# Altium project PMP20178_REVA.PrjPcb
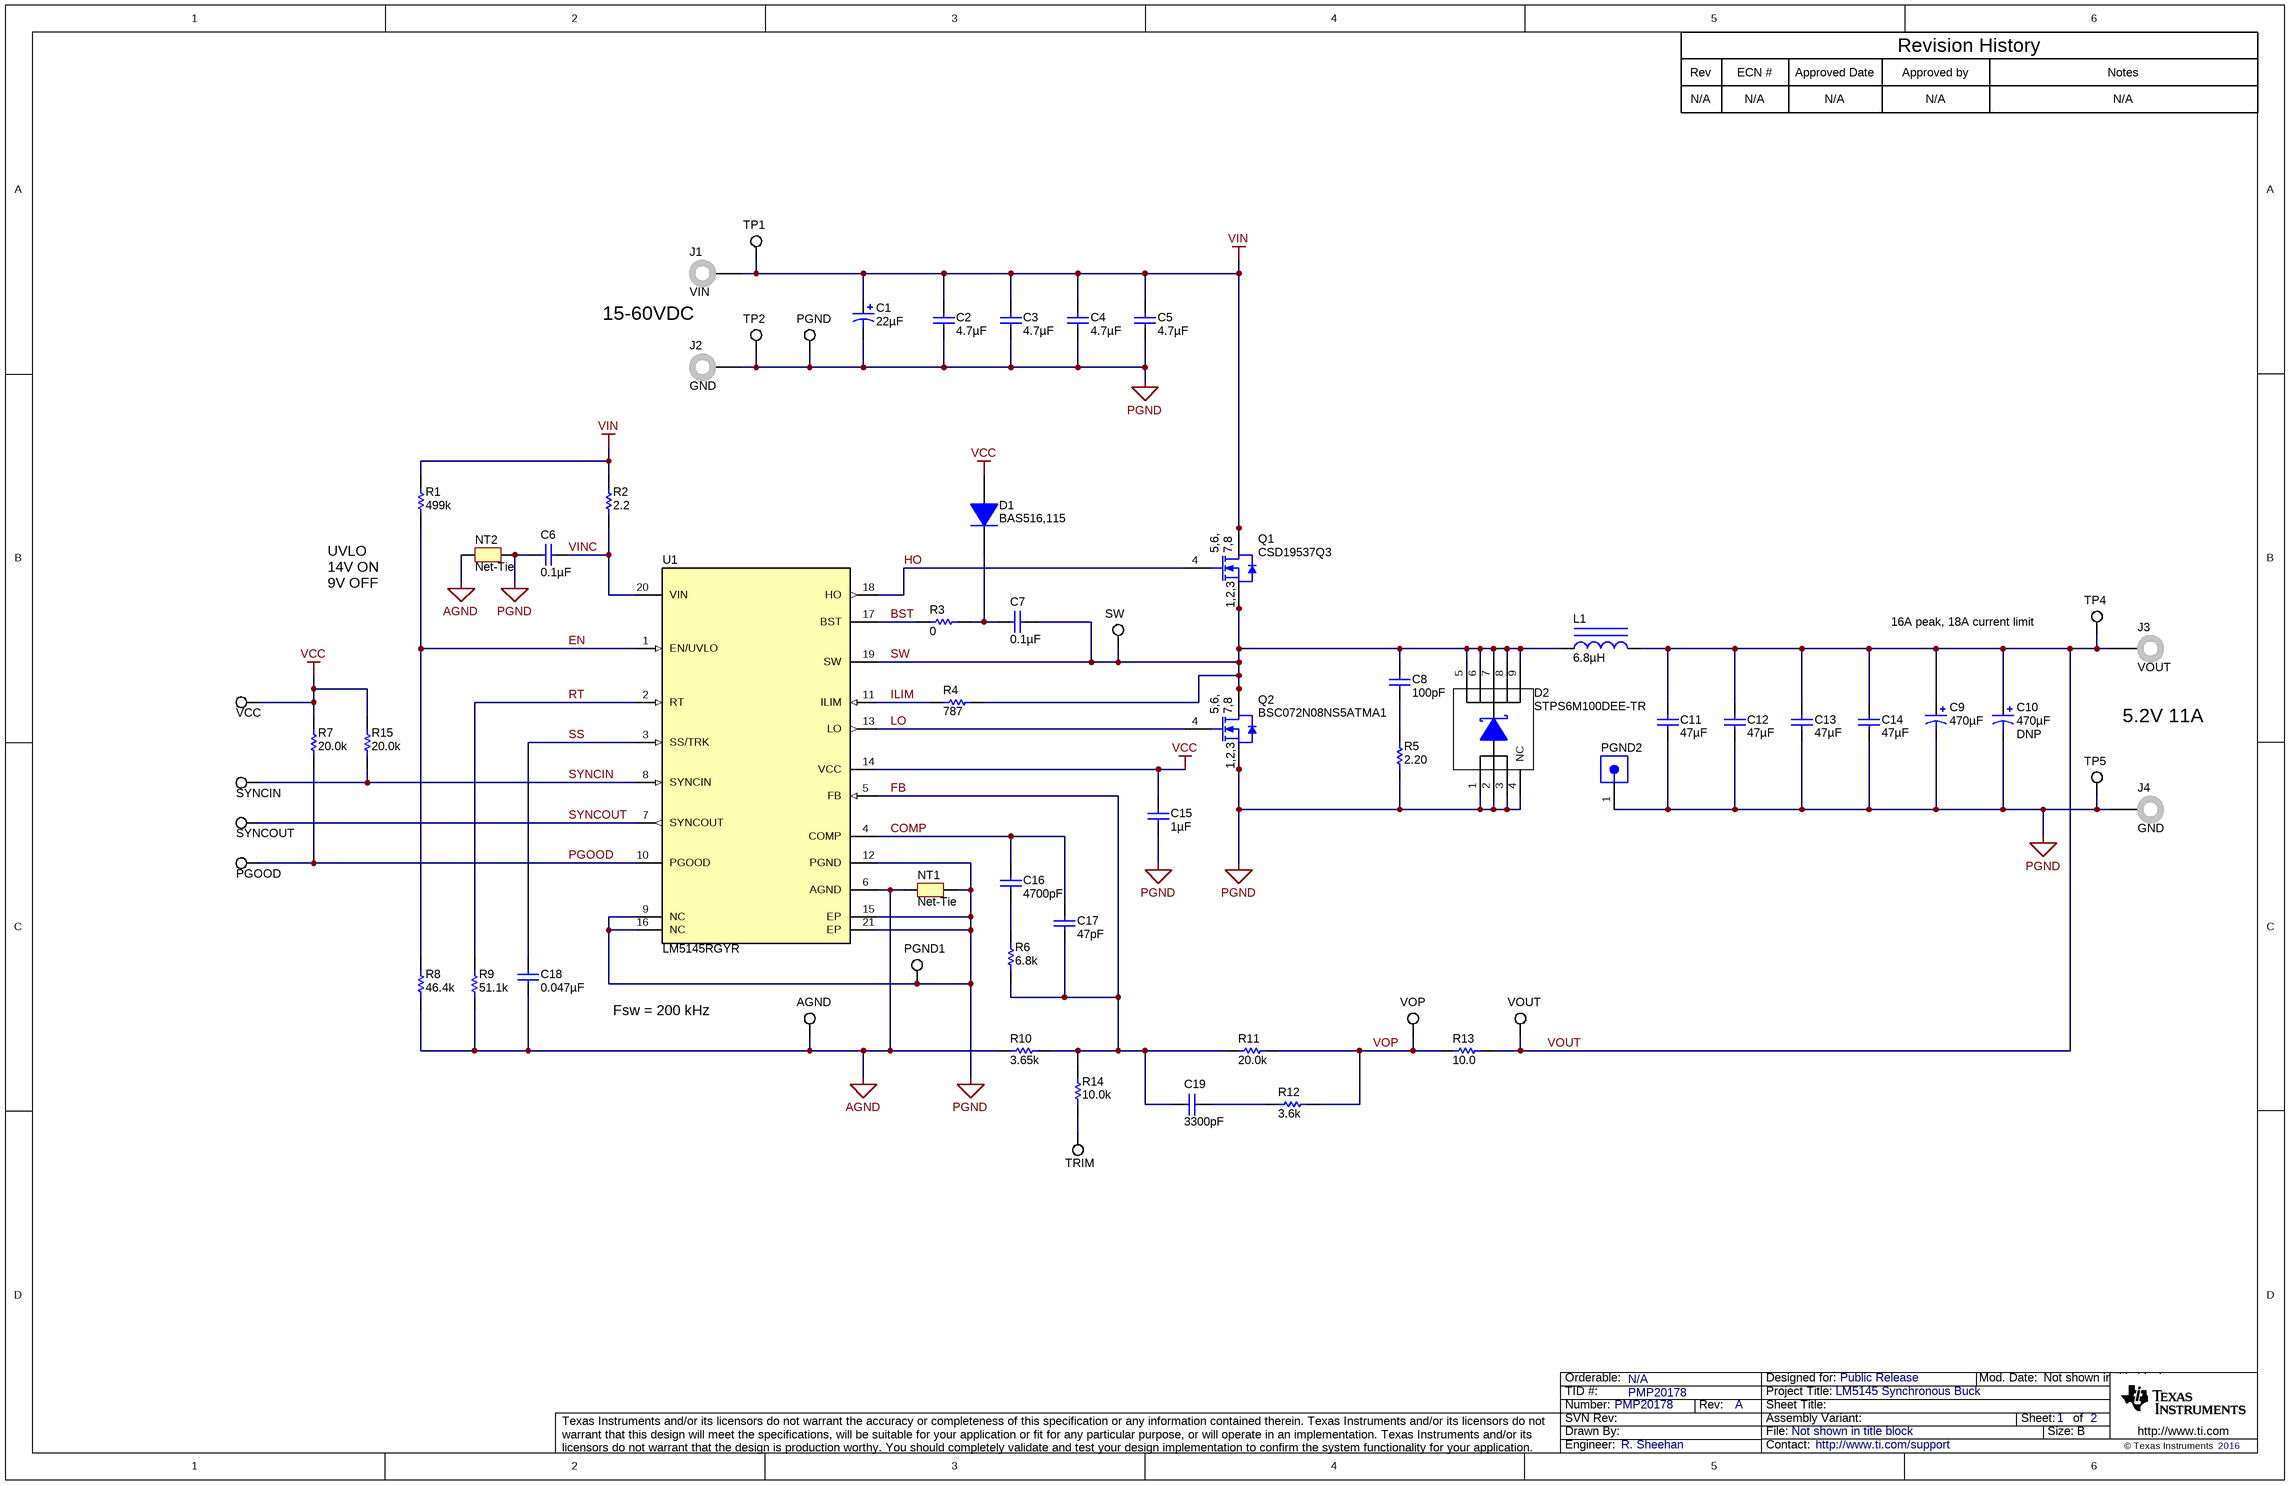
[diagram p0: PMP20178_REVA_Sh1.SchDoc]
CopyrightYear: 2016; EVM_Orderable: N/A; PCB_Layout: R. Sheehan; PCB_Rev: A; PRJ_Customer: Public Release; PRJ_Engineer: R. Sheehan; PRJ_Number: PMP20178; PRJ_Title: LM5145 Synchronous Buck; SCH_Rev: A; TechSupport: http://www.ti.com/support; TID: PMP20178
2 sheets, 79 parts. Net scope: global (net labels, ports and power ports of the same name join across sheets).
Board file: PMP20178_REVA.PcbDoc
Sheets:
  PMP20178_REVA_Sh1.SchDoc
  PMP20178_REVA_Sh2.SchDoc

## Sheet PMP20178_REVA_Sh1.SchDoc
size 431 x 279 mm; Date: Not shown in title block; ApprovedBy: Not shown in title block; CheckedBy: Not shown in title block; Author: Not shown in title block; CompanyName: Not shown in title block; Engineer: Not shown in title block; Organization: Not shown in title block; Address1: Not shown in title block; Address2: Not shown in title block; Address3: Not shown in title block; Address4: Not shown in title block; DocumentNumber: 1; Revision: Use project parameter SCH_Rev; SheetNumber: 1; SheetTotal: 2; PageSetup: Record=PageOptions¦CenterHorizontal=True¦CenterVertical=True¦PrintScale=1.00¦XCorrection=1.00¦YCorrection=1.00¦PrintKind=0¦BorderSize=5000000¦LeftOffset=0¦BottomOffset=0¦Orientation=2¦PaperLength=1000¦PaperWidth=1000¦Scale=100¦PaperSource=15¦PrintQuality=600¦MediaType=1¦DitherType=10¦PaperKind=Letter¦PrintScaleMode=1

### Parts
AGND  5015  [Testpoint_Keystone_Miniature]  (value not drawn)
C1  ValueDisplayed: 22µF  [SM_RADIAL_F]  (hidden comment: EEE-FK2A220P)
C2  ValueDisplayed: 4.7µF  [1210]  (hidden comment: C3225X7S2A475K200AB)
C3  ValueDisplayed: 4.7µF  [1210]  (hidden comment: C3225X7S2A475K200AB)
C4  ValueDisplayed: 4.7µF  [1210]  (hidden comment: C3225X7S2A475K200AB)
C5  ValueDisplayed: 4.7µF  [1210]  (hidden comment: C3225X7S2A475K200AB)
C6  ValueDisplayed: 0.1µF  [0603L]  (hidden comment: GRM188R72A104KA35D)
C7  ValueDisplayed: 0.1µF  [0603L]  (hidden comment: GRM188R72A104KA35D)
C8  ValueDisplayed: 100pF  [0603L]  (hidden comment: C1608C0G2A101F080AA)
C9  ValueDisplayed: 470µF  [7343-20]  (hidden comment: 6TPE470MAZU)
C10  DNP  ValueDisplayed: 470µF  [SM_RADIAL_F]
C11  ValueDisplayed: 47µF  [1210_270]  (hidden comment: GRM32ER71A476KE15L)
C12  ValueDisplayed: 47µF  [1210_270]  (hidden comment: GRM32ER71A476KE15L)
C13  ValueDisplayed: 47µF  [1210_270]  (hidden comment: GRM32ER71A476KE15L)
C14  ValueDisplayed: 47µF  [1210_270]  (hidden comment: GRM32ER71A476KE15L)
C15  ValueDisplayed: 1µF  [0603L]  (hidden comment: C1608X7R1E105K080AB)
C16  ValueDisplayed: 4700pF  [0603L]  (hidden comment: GRM188R71H472KA01D)
C17  ValueDisplayed: 47pF  [0603L]  (hidden comment: GRM1885C1H470JA01D)
C18  ValueDisplayed: 0.047µF  [0603L]  (hidden comment: C1608X7R1H473K080AA)
C19  ValueDisplayed: 3300pF  [0603L]  (hidden comment: GRM188R71H332KA01D)
D1  BAS516,115  [SOD-523]
D2  STPS6M100DEE-TR  [PowerFLAT_3_3x3_3]
J1  VIN  [Keystone575-8]
J2  GND  [Keystone575-8]
J3  VOUT  [Keystone575-8]
J4  GND  [Keystone575-8]
L1  ValueDisplayed: 6.8µH  [PA4344]  (hidden comment: PA4344.682NLT)
NT1  Net-Tie  [Net-Tie_10mil]  (net tie, no BOM)
NT2  Net-Tie  [Net-Tie_50milWide_30milLong]  (net tie, no BOM)
PGND  5015  [Testpoint_Keystone_Miniature]  (value not drawn)
PGND1  5015  [Testpoint_Keystone_Miniature]  (value not drawn)
PGND2  1040  [CONN_1040]  (value not drawn)
PGOOD  5015  [Testpoint_Keystone_Miniature]  (value not drawn)
Q1  CSD19537Q3  [DQG0008A]
Q2  BSC072N08NS5ATMA1  [PG-TDSON-8]
R1  ValueDisplayed: 499k  [0805_HV]  (hidden comment: CRCW0805499KFKEA)
R2  ValueDisplayed: 2.2  [0603L]  (hidden comment: CRCW06032R20JNEA)
R3  ValueDisplayed: 0  [0603L]  (hidden comment: CRCW06030000Z0EA)
R4  ValueDisplayed: 787  [0603L]  (hidden comment: CRCW0603787RFKEA)
R5  ValueDisplayed: 2.20  [0805_HV]  (hidden comment: RC0805FR-072R2L)
R6  ValueDisplayed: 6.8k  [0603L]  (hidden comment: CRCW06036K80JNEA)
R7  ValueDisplayed: 20.0k  [0603L]  (hidden comment: CRCW060320K0FKEA)
R8  ValueDisplayed: 46.4k  [0603L]  (hidden comment: CRCW060346K4FKEA)
R9  ValueDisplayed: 51.1k  [0603L]  (hidden comment: CRCW060351K1FKEA)
R10  ValueDisplayed: 3.65k  [0603L]  (hidden comment: CRCW06033K65FKEA)
R11  ValueDisplayed: 20.0k  [0603L]  (hidden comment: CRCW060320K0FKEA)
R12  ValueDisplayed: 3.6k  [0603L]  (hidden comment: CRCW06033K60JNEA)
R13  ValueDisplayed: 10.0  [0603L]  (hidden comment: CRCW060310R0FKEAHP)
R14  ValueDisplayed: 10.0k  [0603L]  (hidden comment: CRCW060310K0FKEA)
R15  ValueDisplayed: 20.0k  [0603L]  (hidden comment: CRCW060320K0FKEA)
SW  5015  [Testpoint_Keystone_Miniature]  (value not drawn)
SYNCIN  5015  [Testpoint_Keystone_Miniature]  (value not drawn)
SYNCOUT  5015  [Testpoint_Keystone_Miniature]  (value not drawn)
TP1  5015  [Testpoint_Keystone_Miniature]  (value not drawn)
TP2  5015  [Testpoint_Keystone_Miniature]  (value not drawn)
TP4  5015  [Testpoint_Keystone_Miniature]  (value not drawn)
TP5  5015  [Testpoint_Keystone_Miniature]  (value not drawn)
TRIM  5015  [Testpoint_Keystone_Miniature]  (value not drawn)
U1  LM5145RGYR  [RGY0020B]
VCC  5015  [Testpoint_Keystone_Miniature]  (value not drawn)
VOP  5015  [Testpoint_Keystone_Miniature]  (value not drawn)
VOUT  5015  [Testpoint_Keystone_Miniature]  (value not drawn)

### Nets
AGND: AGND.1 C18.2 NT1.2 NT2.2 R8.1 R9.1 R10.1 U1.6(AGND)
PGND: C1.2(-) C2.2 C3.2 C4.2 C5.2 C6.2 C9.2(-) C10.2(-) C11.2 C12.2 C13.2 C14.2 C15.2 D2.1(A) D2.2(A) D2.3(A) D2.4(NC) J2.1 J4.1 NT1.1 NT2.1 PGND.1 PGND1.1 PGND2.1 Q2.1(S) Q2.2(S) Q2.3(S) R5.1 TP2.1 TP5.1 U1.9(NC) U1.12(PGND) U1.15(EP) U1.16(NC) U1.21(EP)
VCC: C15.1 D1.2(A) R7.1 R15.1 U1.14(VCC) VCC.1
VIN: C1.1(+) C2.1 C3.1 C4.1 C5.1 J1.1 Q1.5(D) Q1.6(D) Q1.7(D) Q1.8(D) Q1.9(D) R1.2 R2.2 TP1.1
BST: R3.1 U1.17(BST)
COMP: C16.1 C17.1 U1.4(COMP)
EN: R1.1 R8.2 U1.1(EN/UVLO)
FB: C17.2 C19.2 R6.1 R10.2 R11.1 R14.2 U1.5(FB)
HO: Q1.4(G) U1.18(HO)
ILIM: R4.1 U1.11(ILIM)
LO: Q2.4(G) U1.13(LO)
PGOOD: PGOOD.1 R7.2 U1.10(PGOOD)
RT: R9.2 U1.2(RT)
SS: C18.1 U1.3(SS/TRK)
SW: C7.1 C8.1 D2.5(K) D2.6(K) D2.7(K) D2.8(K) D2.9(K) L1.1 Q1.1(S) Q1.2(S) Q1.3(S) Q2.5(D) Q2.6(D) Q2.7(D) Q2.8(D) Q2.9(D) R4.2 SW.1 U1.19(SW)
SYNCIN: R15.2 SYNCIN.1 U1.8(SYNCIN)
SYNCOUT: SYNCOUT.1 U1.7(SYNCOUT)
VINC: C6.1 R2.1 U1.20(VIN)
VOP: R11.2 R12.2 R13.1 VOP.1
VOUT: C9.1(+) C10.1(+) C11.1 C12.1 C13.1 C14.1 J3.1 L1.2 R13.2 TP4.1 VOUT.1
NetC7_2: C7.2 D1.1(K) R3.2
NetC8_2: C8.2 R5.2
NetC16_2: C16.2 R6.2
NetC19_1: C19.1 R12.1
NetR14_1: R14.1 TRIM.1

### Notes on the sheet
- Rev
- N/A
- ECN #
- Approved Date
- Approved by
- Revision History
- Notes
- 15-60VDC
- (near R1) UVLO
  14V ON
  9V OFF
- (near TP4) 16A peak, 18A current limit
- 5.2V 11A
- Fsw = 200 kHz

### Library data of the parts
AGND PGND PGND1 PGOOD SW SYNCIN SYNCOUT TP1 TP2 TP4 TP5 TRIM VCC VOP VOUT = 5015: Test Point, Miniature, SMT; Manufacturer: Keystone; CompType: Test Point Loop
C1 = EEE-FK2A220P: CAP, AL, 22 µF, 100 V, +/- 20%, 1.3 ohm, SMD; Manufacturer: Panasonic; CompType: Capacitor; Value: 22uF; U/M: EA; Tolerance_%: 20; VDC_V: 100; ESR_ohm: 1.3; Polarized: Y; Cap_F: 0.000022; Value1: 1.3 ohm; Value2: 100V; IRMS_A: 0.13; TaMin_C: -55; TaMax_C: 105; Cap_Case: F; AEC Category: Q200
C2-C5 = C3225X7S2A475K200AB: CAP, CERM, 4.7 µF, 100 V, +/- 10%, X7S, 1210; Manufacturer: TDK; Polarized: N; CompType: Capacitor; Value: 4.7uF; U/M: EA; Cap_F: 0.0000047; Tolerance_%: 10; Value1: Unknown; VDC_V: 100; Value2: 100V; TaMin_C: -55; TaMax_C: 125; AEC Category: Q200
C6 C7 = GRM188R72A104KA35D: CAP, CERM, 0.1 µF, 100 V, +/- 10%, X7R, 0603; Manufacturer: MuRata; Polarized: N; CompType: Capacitor; Value: 0.1uF; U/M: EA; Cap_F: 0.0000001; Tolerance_%: 10; Value1: Unknown; VDC_V: 100; Value2: 100V; TaMin_C: -55; TaMax_C: 125; Cap_Case: 0603; AEC Category: Q200
C8 = C1608C0G2A101F080AA: CAP, CERM, 100 pF, 100 V, +/- 1%, C0G/NP0, 0603; Manufacturer: TDK; Polarized: N; CompType: Capacitor; Value: 100pF; U/M: EA; Cap_F: 0.0000000001; Tolerance_%: 1; Value1: Unknown; VDC_V: 100; Value2: 100V; TaMin_C: -55; TaMax_C: 125; Cap_Case: 0603; AEC Category: Q200
C9 = 6TPE470MAZU: CAP, Tantalum Polymer, 470 µF, 6.3 V, +/- 20%, 0.035 ohm, 7343-20 SMD; Manufacturer: Panasonic; Polarized: Y; CompType: Capacitor; Value: 470uF; U/M: EA; Cap_F: 0.00047; Tolerance_%: 20; VDC_V: 6.3; Value2: 6.3V; ESR_ohm: 0.035; IRMS_A: 1.7; TaMin_C: -55; TaMax_C: 105; Cap_Case: D; AEC Category: Q200; AEC Qualified: N
C10 = EEE-FK1A471P: CAP, AL, 470 µF, 10 V, +/- 20%, 0.16 ohm, SMD; Manufacturer: Panasonic; Polarized: Y; CompType: Capacitor; Value: 470uF; U/M: EA; Cap_F: 0.00047; Tolerance_%: 20; VDC_V: 10; Value2: 10V; ESR_ohm: 0.16; IRMS_A: 0.6; TaMin_C: -55; TaMax_C: 105; Cap_Case: F; AEC Category: Q200
C11-C14 = GRM32ER71A476KE15L: CAP, CERM, 47 µF, 10 V, +/- 10%, X7R, 1210; Manufacturer: MuRata; Polarized: N; CompType: Capacitor; Value: 47uF; U/M: EA; Cap_F: 0.000047; Tolerance_%: 10; Value1: Unknown; Value2: 10V; TaMin_C: -55; TaMax_C: 125; Cap_Case: 1210; AEC Category: Q200
C15 = C1608X7R1E105K080AB: CAP, CERM, 1 µF, 25 V, +/- 10%, X7R, 0603; Manufacturer: TDK; Polarized: N; CompType: Capacitor; Value: 1uF; U/M: EA; Cap_F: 0.000001; Tolerance_%: 10; Value1: Unknown; VDC_V: 25; Value2: 25V; TaMin_C: -55; TaMax_C: 125; Cap_Case: 0603; AEC Category: Q200
C16 = GRM188R71H472KA01D: CAP, CERM, 4700 pF, 50 V, +/- 10%, X7R, 0603; Manufacturer: MuRata; Polarized: N; CompType: Capacitor; Value: 4700pF; U/M: EA; Cap_F: 0.0000000047; Tolerance_%: 10; Value1: Unknown; VDC_V: 50; Value2: 50V; TaMin_C: -55; TaMax_C: 125; Cap_Case: 0603; AEC Category: Q200
C17 = GRM1885C1H470JA01D: CAP, CERM, 47 pF, 50 V, +/- 5%, C0G/NP0, 0603; Manufacturer: MuRata; Polarized: N; CompType: Capacitor; Value: 47pF; U/M: EA; Cap_F: 0.000000000047; Tolerance_%: 5; Value1: Unknown; VDC_V: 50; Value2: 50V; TaMin_C: -55; TaMax_C: 125; Cap_Case: 0603; AEC Category: Q200
C18 = C1608X7R1H473K080AA: CAP, CERM, 0.047 µF, 50 V, +/- 10%, X7R, 0603; Manufacturer: TDK; Polarized: N; CompType: Capacitor; Value: 0.047uF; U/M: EA; Cap_F: 0.000000047; Tolerance_%: 10; ESR_ohm: 0.049007; Value1: 0.049007 ohm; VDC_V: 50; Value2: 50V; IRMS_A: 0.767528; TaMin_C: -55; TaMax_C: 125; Cap_Case: 0603; AEC Category: Q200
C19 = GRM188R71H332KA01D: CAP, CERM, 3300 pF, 50 V, +/- 10%, X7R, 0603; Manufacturer: MuRata; Polarized: N; CompType: Capacitor; Value: 3300pF; U/M: EA; Cap_F: 0.0000000033; Tolerance_%: 10; Value1: Unknown; VDC_V: 50; Value2: 50V; TaMin_C: -55; TaMax_C: 125; Cap_Case: 0603; AEC Category: Q200
D1 = BAS516,115: Diode, Switching, 100 V, 0.25 A, SOD-523; Manufacturer: NXP Semiconductor; U/M: EA; Vf_V: 1.25; Value: 100V; Value1: 0.25A; Value2: 1.25V; Io_A: 0.25; Vr_V: 100; TJmax_C: 150; AEC Category: Q101
D2 = STPS6M100DEE-TR: Diode, Schottky, 100 V, 6 A, 8-PowerTDFN; Manufacturer: STMicroelectronics; U/M: EA; Vf_V: 0.64; Value: 100V; Value1: 6A; Value2: 0.64V; Io_A: 6; Vr_V: 100; TJmax_C: 150; RJC_CperW: 4; AEC Category: Q101; AEC Qualified: N; SymbolCreator: Altium
J1-J4 = 575-8: Standard Banana Jack, Uninsulated, 8.9mm; Manufacturer: Keystone; CompType: Connector
L1 = PA4344.333NLT: Inductor, Shielded, 6.8 µH, 19.0 A, 0.0092 ohm, AEC-Q200 Grade 1, SMD; Manufacturer: Pulse Engineering; Value: 6.8uH; Ind_H: 33.0E-6; Imax_A: 19.0; Irms: 19.0A @ 40C rise; Isat: 32A @ 30% inductance drop; DCR_ohm: 0.0092; Value2: 19.0 A; AEC Category: Q200; AEC Qualified: Y; AEC Grade: 1
NT1 NT2 = Net-Tie: Single point connection between nets.; SymbolCreator: codlsc
PGND2 = 1040: TEST POINT SLOTTED .118", TH; Manufacturer: Keystone; SymbolCreator: a0412235; CompType: Test Point Loop
Q1 = CSD19537Q3: MOSFET, N-CH, 100 V, 50 A, VSON-CLIP-8; Manufacturer: Texas Instruments; Alternate Manufacturer: None; U/M: EA; ChType: N; Value: 100V; VdsMax_V: 100; Value1: ? ohm; Value2: 16 nC; QgTyp_nC: 16; Vgs_V: 20; IdsMax_A: 50; AEC Category: Q101
Q2 = BSC072N08NS5ATMA1: MOSFET, N-CH, 80 V, 74 A, PG-TDSON-8; Manufacturer: Infineon Technologies; Alternate Manufacturer: None; U/M: EA; ChType: N; Value: 80V; VdsMax_V: 80; Value1: ? ohm; Value2: 24 nC; QgTyp_nC: 24; Vgs_V: 20; IdsMax_A: 74; AEC Category: Q101; SizeAreaWB_mm2: 55.131; SizeArea_mm2: 29.351; SizeX_mm: 5.99; SizeY_mm: 4.9; SizeZ_mm: 1.12
R1 = CRCW0805499KFKEA: RES, 499 k, 1%, 0.125 W, 0805; Manufacturer: Vishay-Dale; CompType: Resistor; Value: 499k; Res_ohm: 499000; Tolerance_%: 1; Power_W: 0.125; Value2: 0.125W; VDC_V: 150; TempCo: 100 ppm/C; EIA_Code: E96; U/M: EA; AEC Category: Q200
R2 = CRCW06032R20JNEA: RES, 2.2, 5%, 0.1 W, 0603; Manufacturer: Vishay-Dale; CompType: Resistor; Value: 2.2; Value_Code: 2R20; Tolerance_%: 5; Power_W: 0.1; Value2: 0.1W; VDC_V: 75; TempCo: 200 ppm/C; EIA_Code: E24; U/M: EA; AEC Category: Q200
R3 = CRCW06030000Z0EA: RES, 0, 5%, 0.1 W, 0603; Manufacturer: Vishay-Dale; CompType: Resistor; Value: 0; Value_Code: 0000; Tolerance_%: 5; Power_W: 0.1; Value2: 0.1W; VDC_V: 75; TempCo: 200 ppm/C; EIA_Code: E24; U/M: EA; AEC Category: Q200
R4 = CRCW0603787RFKEA: RES, 787, 1%, 0.1 W, 0603; Manufacturer: Vishay-Dale; CompType: Resistor; Value: 787; Value_Code: 787R; Tolerance_%: 1; Power_W: 0.1; Value2: 0.1W; VDC_V: 75; TempCo: 100 ppm/C; EIA_Code: E96; U/M: EA; AEC Category: Q200; SizeArea_mm2: 1.28; SizeX_mm: 1.6; SizeY_mm: 0.8
R5 = RC0805FR-072R2L: RES, 2.20, 1%, 0.125 W, 0805; Manufacturer: Yageo America; CompType: Resistor; Value: 2.20; Res_ohm: 2.2; Value_Code: 2R20; Tolerance_%: 1; Power_W: 0.125; Value2: 0.125W; VDC_V: 150; TempCo: 200 ppm/C; U/M: EA; AEC Category: Q200
R6 = CRCW06036K80JNEA: RES, 6.8 k, 5%, 0.1 W, 0603; Manufacturer: Vishay-Dale; CompType: Resistor; Value: 6.8k; Res_ohm: 6800; Value_Code: 6k80; Tolerance_%: 5; Power_W: 0.1; Value2: 0.1W; VDC_V: 75; TempCo: 200 ppm/C; EIA_Code: E24; U/M: EA; AEC Category: Q200
R7 R11 R15 = CRCW060320K0FKEA: RES, 20.0 k, 1%, 0.1 W, 0603; Manufacturer: Vishay-Dale; CompType: Resistor; Value: 20.0k; Res_ohm: 20000; Value_Code: 20k0; Tolerance_%: 1; Power_W: 0.1; Value2: 0.1W; VDC_V: 75; TempCo: 100 ppm/C; EIA_Code: E96; U/M: EA; AEC Category: Q200
R8 = CRCW060346K4FKEA: RES, 46.4 k, 1%, 0.1 W, 0603; Manufacturer: Vishay-Dale; CompType: Resistor; Value: 46.4k; Res_ohm: 46400; Value_Code: 46k4; Tolerance_%: 1; Power_W: 0.1; Value2: 0.1W; VDC_V: 75; TempCo: 100 ppm/C; EIA_Code: E96; U/M: EA; AEC Category: Q200; SizeArea_mm2: 1.28; SizeX_mm: 1.6; SizeY_mm: 0.8
R9 = CRCW060351K1FKEA: RES, 51.1 k, 1%, 0.1 W, 0603; Manufacturer: Vishay-Dale; CompType: Resistor; Value: 51.1k; Res_ohm: 51100; Value_Code: 51k1; Tolerance_%: 1; Power_W: 0.1; Value2: 0.1W; VDC_V: 75; TempCo: 100 ppm/C; EIA_Code: E96; U/M: EA; AEC Category: Q200; SizeArea_mm2: 1.28; SizeX_mm: 1.6; SizeY_mm: 0.8
R10 = CRCW06033K65FKEA: RES, 3.65 k, 1%, 0.1 W, 0603; Manufacturer: Vishay-Dale; CompType: Resistor; Value: 3.65k; Res_ohm: 3650; Value_Code: 3k65; Tolerance_%: 1; Power_W: 0.1; Value2: 0.1W; VDC_V: 75; TempCo: 100 ppm/C; EIA_Code: E96; U/M: EA; AEC Category: Q200; SizeArea_mm2: 1.28; SizeX_mm: 1.6; SizeY_mm: 0.8
R12 = CRCW06033K60JNEA: RES, 3.6 k, 5%, 0.1 W, 0603; Manufacturer: Vishay-Dale; CompType: Resistor; Value: 3.6k; Res_ohm: 3600; Value_Code: 3k60; Tolerance_%: 5; Power_W: 0.1; Value2: 0.1W; VDC_V: 75; TempCo: 200 ppm/C; EIA_Code: E24; U/M: EA; AEC Category: Q200
R13 = CRCW060310R0FKEAHP: RES, 10.0, 1%, 0.25 W, 0603; Manufacturer: Vishay-Dale; CompType: Resistor; Value: 10.0; Res_ohm: 10; Value_Code: 10R0; Tolerance_%: 1; Power_W: 0.25; Value2: 0.25W; VDC_V: 75; TempCo: 100 ppm/C; EIA_Code: E96; U/M: EA; AEC Category: Q200
R14 = CRCW060310K0FKEA: RES, 10.0 k, 1%, 0.1 W, 0603; Manufacturer: Vishay-Dale; CompType: Resistor; Value: 10.0k; Res_ohm: 10000; Value_Code: 10k0; Tolerance_%: 1; Power_W: 0.1; Value2: 0.1W; VDC_V: 75; TempCo: 100 ppm/C; EIA_Code: E96; U/M: EA; AEC Category: Q200
U1 = LM5145RGYR: Wide Input Range Synchronous Buck Controller, RGY0020B; Alternate PartNumber: LM5145RGYT; Manufacturer: Texas Instruments; SymbolCreator: Altium; CompType: IC; U/M: EA

## Sheet PMP20178_REVA_Sh2.SchDoc
size 431 x 279 mm; Date: Not shown in title block; ApprovedBy: Not shown in title block; CheckedBy: Not shown in title block; Author: Not shown in title block; CompanyName: Not shown in title block; Engineer: Not shown in title block; Organization: Not shown in title block; Address1: Not shown in title block; Address2: Not shown in title block; Address3: Not shown in title block; Address4: Not shown in title block; DocumentNumber: 2; Revision: Use project parameter SCH_Rev; SheetNumber: 2; SheetTotal: 2; PageSetup: Record=PageOptions¦CenterHorizontal=True¦CenterVertical=True¦PrintScale=1.00¦XCorrection=1.00¦YCorrection=1.00¦PrintKind=0¦BorderSize=5000000¦LeftOffset=0¦BottomOffset=0¦Orientation=2¦PaperLength=1000¦PaperWidth=1000¦Scale=100¦PaperSource=15¦PrintQuality=600¦MediaType=1¦DitherType=10¦PaperKind=Letter¦PrintScaleMode=1
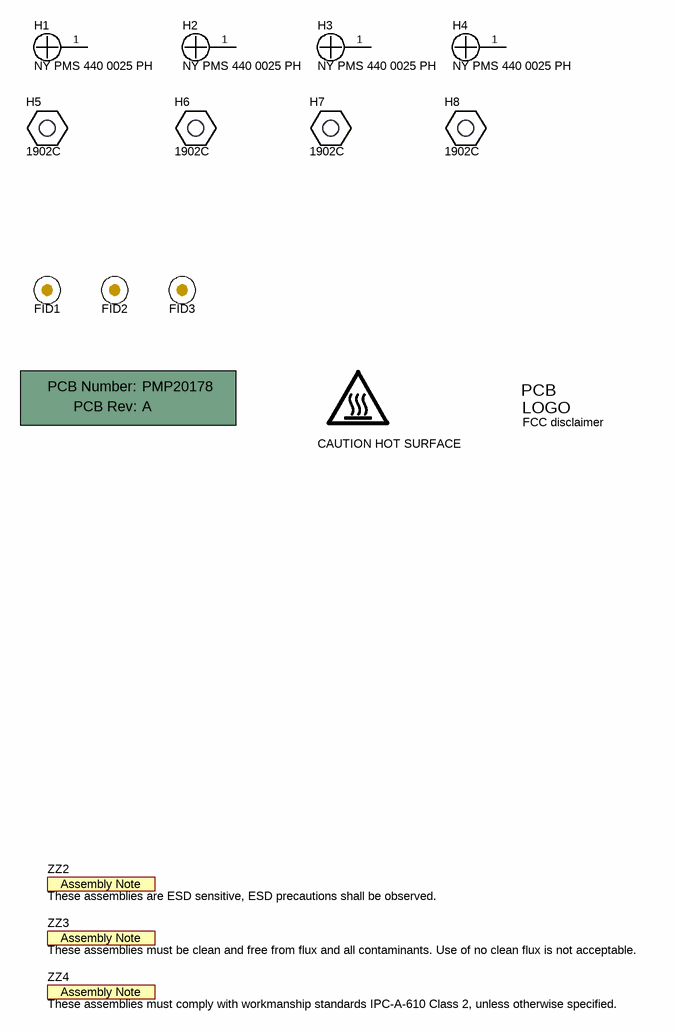
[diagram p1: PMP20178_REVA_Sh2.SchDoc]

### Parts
!PCB  Printed Circuit Board  (value not drawn)  (mechanical)
FID1  Fiducial  [Fiducial10-20]  (value not drawn)
FID2  Fiducial  [Fiducial10-20]  (value not drawn)
FID3  Fiducial  [Fiducial10-20]  (value not drawn)
H1  NY PMS 440 0025 PH  [NY PMS 440 0025 PH]
H2  NY PMS 440 0025 PH  [NY PMS 440 0025 PH]
H3  NY PMS 440 0025 PH  [NY PMS 440 0025 PH]
H4  NY PMS 440 0025 PH  [NY PMS 440 0025 PH]
H5  1902C  [Keystone_1902C]
H6  1902C  [Keystone_1902C]
H7  1902C  [Keystone_1902C]
H8  1902C  [Keystone_1902C]
Logo2  CAUTION HOT SURFACE  [IEC_HotSurface_Small]  (no BOM)
Logo3  FCC disclaimer  [FCC_disclaimer_stacked]  (no BOM)
ZZ2  These assemblies are ESD sensitive, ESD precautions shall be observed.  [AssemblyNote]  (no BOM)
ZZ3  These assemblies must be clean and free from flux and all contaminants. Use of no clean flux is not acceptable.  [AssemblyNote]  (no BOM)
ZZ4  These assemblies must comply with workmanship standards IPC-A-610 Class 2, unless otherwise specified.  [AssemblyNote]  (no BOM)

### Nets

Not connected (* = marked no-connect by the designer): H1 1; H2 1; H3 1; H4 1

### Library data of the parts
!PCB = PCB: Manufacturer: Any; PartNumber: PMP20178; SymbolCreator: a0412235
FID1-FID3 = Fiducial: Fiducial mark.  There is nothing to buy or mount.; SymbolCreator: codlsc
H1-H4 = NY PMS 440 0025 PH: Machine Screw, Round, #4-40 x 1/4, Nylon, Philips panhead; Manufacturer: B&F Fastener Supply; CompType: Hardware; SymbolCreator: codlsc; U/M: EA
H5-H8 = 1902C: Standoff, Hex, 0.5"L #4-40 Nylon; Manufacturer: Keystone; CompType: Hardware
Logo2 = IEC_HotSurface: IEC 61010-1 Hot Surface Warning; SymbolCreator: a0412235
Logo3 = FCC_disclaimer: SymbolCreator: codlsc
ZZ2-ZZ4 = AssemblyNote: SymbolCreator: codlsc

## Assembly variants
001: not fitted C10 FID1 FID2 FID3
